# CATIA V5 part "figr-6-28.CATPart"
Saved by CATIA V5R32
Part number: Part1
Bounding box of the stored display mesh (mm): x 0 to 45, y 0 to 76.536, z 0 to 111.001
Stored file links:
  D:\PROJECTS\Project 2022\CATIA V5 6R 2022\Resources\Part Files\c06_catia_v5_6r2022_prt\figr-6-28.CATPart
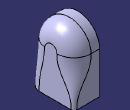
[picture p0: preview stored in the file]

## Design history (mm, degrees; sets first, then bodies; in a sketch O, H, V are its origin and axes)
Body1 (main body)
  Sketch1 on yz-plane, origin (0, 0, 0), H (0, 1, 0), V (0, 0, 1)
    line L1 (0, 0) -> (76.5361, 0)
    line L2 (76.5361, 0) -> (76.5361, 72.7325)
    line L3 (0, 0) -> (0, 72.7325)
    arc A1 centre (38.2681, 72.7325) radius 38.2681 from (76.5361, 72.7325) to (0, 72.7325) ccw
    horizontal: L1 H
    vertical: L2 V, L3 V
    tangency: A1 L3, A1 L2
  Pad1: profile Sketch1, direction (1, 0, 0), length 45
  Fillet1: on edge [face of Pad1 | face of Pad1] (x3)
